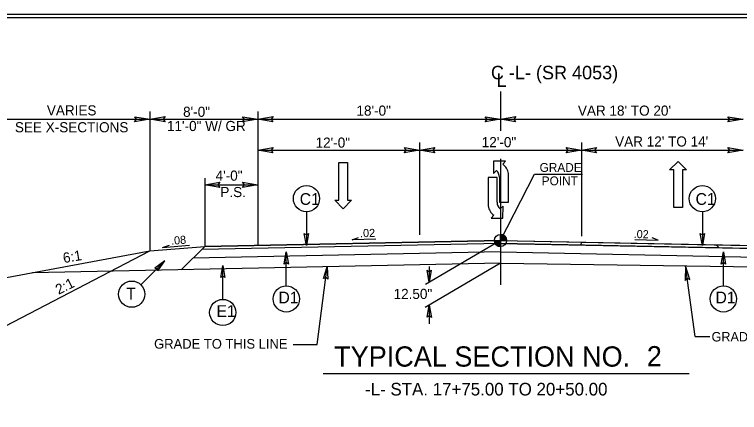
# Model space of a CAD drawing. Extents: x 981824 to 982276, y 44828 to 45204.
# Drawn here: x 982128.96 to 982171.98, y 45064.58 to 45088.17 of the extents above; entities that cross this region are included whole.
import ezdxf

# ---------------------------------------------------------------- set-up
doc = ezdxf.new("R2010")
doc.units = 0
for name, color, linetype in [('Default', 7, 'Continuous'), ('Old_Level_1', 7, 'Continuous'), ('Old_Level_11', 7, 'Continuous'), ('Old_Level_18', 7, 'Continuous'), ('Old_Level_2', 7, 'Continuous'), ('Old_Level_20', 7, 'Continuous'), ('Old_Level_21', 7, 'Continuous'), ('Old_Level_3', 7, 'Continuous'), ('Old_Level_50', 7, 'Continuous'), ('Prop Dimension Text', 7, 'Continuous'), ('Prop Lane Arrow CELL', 7, 'Continuous'), ('Prop Lane Arrow Through CELL', 7, 'Continuous'), ('Prop Roadway Profile Bench Mark Info Text', 7, 'Continuous'), ('Typical Terminator CELL', 7, 'Continuous')]:
    doc.layers.add(name, color=color, linetype=linetype)

msp = doc.modelspace()

# ---------------------------------------------------------------- linework, layer by layer
at = {"layer": 'Default'}
for points in [[(982150.402, 45074.86), (982149.001, 45074.811), (982149.368, 45074.949)], [(982165.76, 45074.838), (982167.161, 45074.789), (982166.795, 45074.928)]]:
    msp.add_lwpolyline(points, dxfattribs=at)
at = {"layer": 'Old_Level_1'}
for p, q in [((982157.794, 45083.599), (982157.794, 45081.277)), ((982136.994, 45082.429), (982136.994, 45074.163)), ((982143.394, 45082.429), (982143.394, 45074.486)), ((982127.455, 45081.961), (982136.994, 45081.961)), ((982136.994, 45081.961), (982143.394, 45081.961)), ((982143.394, 45081.961), (982157.794, 45081.961)), ((982157.794, 45081.961), (982172.194, 45081.961)), ((982152.994, 45080.576), (982152.994, 45075.114)), ((982162.594, 45080.576), (982162.594, 45075.027)), ((982143.394, 45080.13), (982152.994, 45080.13)), ((982152.994, 45080.13), (982162.594, 45080.13)), ((982162.594, 45080.13), (982172.194, 45080.13)), ((982157.794, 45079.618), (982157.794, 45072.147)), ((982157.794, 45074.774), (982159.823, 45078.716)), ((982140.245, 45078.468), (982140.245, 45074.423)), ((982140.245, 45078.078), (982143.394, 45078.078)), ((982157.794, 45074.774), (982157.794, 45075.134)), ((982157.794, 45074.774), (982140.255, 45074.424)), ((982157.794, 45074.774), (982153.354, 45072.168)), ((982157.434, 45074.774), (982157.794, 45074.774)), ((982157.793, 45074.414), (982157.794, 45074.774)), ((982157.794, 45074.774), (982157.793, 45074.414)), ((982157.794, 45074.774), (982175.392, 45074.422)), ((982158.154, 45074.774), (982157.794, 45074.774)), ((982136.994, 45074.163), (982140.255, 45074.424)), ((982137.743, 45074.362), (982139.34, 45074.504)), ((982137.743, 45074.362), (982138.165, 45074.504)), ((982140.245, 45074.423), (982138.856, 45073.042)), ((982157.794, 45074.602), (982140.069, 45074.248)), ((982157.791, 45074.601), (982175.567, 45074.247)), ((982127.455, 45069.205), (982136.994, 45074.163)), ((982127.455, 45072.384), (982136.994, 45074.163)), ((982157.794, 45074.105), (982139.536, 45073.718)), ((982157.794, 45074.105), (982176.095, 45073.719)), ((982157.794, 45073.422), (982130.033, 45072.865)), ((982157.794, 45073.422), (982153.319, 45070.796)), ((982157.794, 45073.422), (982184.096, 45073.052)), ((982146.923, 45068.604), (982147.517, 45073.216)), ((982153.567, 45073.232), (982153.567, 45072.292)), ((982169.345, 45069.089), (982168.78, 45073.267)), ((982153.567, 45070.941), (982153.567, 45069.828)), ((982169.345, 45069.089), (982170.214, 45069.089)), ((982145.505, 45068.604), (982146.923, 45068.604))]:
    msp.add_line(p, q, dxfattribs=at)
for points in [[(982157.797, 45075.134), (982157.797, 45075.134), (982157.797, 45074.774)], [(982157.804, 45075.134), (982157.804, 45074.774)], [(982157.811, 45075.133), (982157.811, 45074.774)], [(982157.819, 45075.133), (982157.819, 45074.774)], [(982157.826, 45075.132), (982157.826, 45074.774)], [(982157.833, 45075.132), (982157.833, 45074.774)], [(982157.84, 45075.131), (982157.84, 45074.774)], [(982157.847, 45075.13), (982157.847, 45074.774)], [(982157.855, 45075.129), (982157.855, 45074.774)], [(982157.862, 45075.128), (982157.862, 45074.774)], [(982157.869, 45075.126), (982157.869, 45074.774)], [(982157.876, 45075.124), (982157.876, 45074.774)], [(982157.883, 45075.123), (982157.883, 45074.774)], [(982157.435, 45074.774), (982157.435, 45074.735)], [(982157.443, 45074.774), (982157.443, 45074.692)], [(982157.45, 45074.774), (982157.45, 45074.667)], [(982157.457, 45074.774), (982157.457, 45074.645)], [(982157.464, 45074.774), (982157.464, 45074.628)], [(982157.471, 45074.774), (982157.471, 45074.613)], [(982157.479, 45074.774), (982157.479, 45074.6)], [(982157.486, 45074.774), (982157.486, 45074.587)], [(982157.493, 45074.774), (982157.493, 45074.576)], [(982157.5, 45074.774), (982157.5, 45074.565)], [(982157.507, 45074.774), (982157.507, 45074.556)], [(982157.515, 45074.774), (982157.515, 45074.547)], [(982157.522, 45074.774), (982157.522, 45074.538)], [(982157.529, 45074.774), (982157.529, 45074.53)], [(982157.536, 45074.774), (982157.536, 45074.522)], [(982157.543, 45074.774), (982157.543, 45074.515)], [(982157.551, 45074.774), (982157.551, 45074.508)], [(982157.558, 45074.774), (982157.558, 45074.502)], [(982157.565, 45074.774), (982157.565, 45074.496)], [(982157.572, 45074.774), (982157.572, 45074.49)], [(982157.579, 45074.774), (982157.579, 45074.484)], [(982157.587, 45074.774), (982157.587, 45074.48)], [(982157.594, 45074.774), (982157.594, 45074.475)], [(982157.601, 45074.774), (982157.601, 45074.47)], [(982157.608, 45074.774), (982157.608, 45074.465)], [(982157.615, 45074.774), (982157.615, 45074.461)], [(982157.623, 45074.774), (982157.623, 45074.457)], [(982157.63, 45074.774), (982157.63, 45074.453)], [(982157.637, 45074.774), (982157.637, 45074.45)], [(982157.644, 45074.774), (982157.644, 45074.447)], [(982157.651, 45074.774), (982157.651, 45074.444)], [(982157.659, 45074.774), (982157.659, 45074.44)], [(982157.666, 45074.774), (982157.666, 45074.437)], [(982157.673, 45074.774), (982157.673, 45074.435)], [(982157.68, 45074.774), (982157.68, 45074.432)], [(982157.687, 45074.774), (982157.687, 45074.43)], [(982157.695, 45074.774), (982157.695, 45074.428)], [(982157.702, 45074.774), (982157.702, 45074.426)], [(982157.709, 45074.774), (982157.709, 45074.424)], [(982157.716, 45074.774), (982157.716, 45074.423)], [(982157.723, 45074.774), (982157.723, 45074.421)], [(982157.731, 45074.774), (982157.731, 45074.42)], [(982157.738, 45074.774), (982157.738, 45074.419)], [(982157.745, 45074.774), (982157.745, 45074.417)], [(982157.752, 45074.774), (982157.752, 45074.416)], [(982157.759, 45074.774), (982157.759, 45074.416)], [(982157.767, 45074.774), (982157.767, 45074.415)], [(982157.774, 45074.774), (982157.774, 45074.415)], [(982157.781, 45074.774), (982157.781, 45074.414)], [(982157.788, 45074.774), (982157.788, 45074.414), (982157.788, 45074.414)], [(982157.891, 45075.12), (982157.891, 45074.774)], [(982157.898, 45075.119), (982157.898, 45074.774)], [(982157.905, 45075.116), (982157.905, 45074.774)], [(982157.912, 45075.114), (982157.912, 45074.774)], [(982157.919, 45075.112), (982157.919, 45074.774)], [(982157.927, 45075.108), (982157.927, 45074.774)], [(982157.934, 45075.105), (982157.934, 45074.774)], [(982157.941, 45075.102), (982157.941, 45074.774)], [(982157.948, 45075.099), (982157.948, 45074.774)], [(982157.955, 45075.096), (982157.955, 45074.774)], [(982157.963, 45075.092), (982157.963, 45074.774)], [(982157.97, 45075.088), (982157.97, 45074.774)], [(982157.977, 45075.084), (982157.977, 45074.774)], [(982157.984, 45075.08), (982157.984, 45074.774)], [(982157.991, 45075.075), (982157.991, 45074.774)], [(982157.999, 45075.07), (982157.999, 45074.774)], [(982158.006, 45075.064), (982158.006, 45074.774)], [(982158.013, 45075.06), (982158.013, 45074.774)], [(982158.02, 45075.054), (982158.02, 45074.774)], [(982158.027, 45075.048), (982158.027, 45074.774)], [(982158.035, 45075.041), (982158.035, 45074.774)], [(982158.042, 45075.035), (982158.042, 45074.774)], [(982158.049, 45075.028), (982158.049, 45074.774)], [(982158.056, 45075.02), (982158.056, 45074.774)], [(982158.063, 45075.012), (982158.063, 45074.774)], [(982158.071, 45075.004), (982158.071, 45074.774)], [(982158.078, 45074.995), (982158.078, 45074.774)], [(982158.085, 45074.985), (982158.085, 45074.774)], [(982158.092, 45074.975), (982158.092, 45074.774)], [(982158.099, 45074.964), (982158.099, 45074.774)], [(982158.107, 45074.952), (982158.107, 45074.774)], [(982158.114, 45074.939), (982158.114, 45074.774)], [(982158.121, 45074.924), (982158.121, 45074.774)], [(982158.128, 45074.907), (982158.128, 45074.774)], [(982158.135, 45074.887), (982158.135, 45074.774)], [(982158.143, 45074.862), (982158.143, 45074.774)], [(982158.15, 45074.825), (982158.15, 45074.774)]]:
    msp.add_lwpolyline(points, dxfattribs=at)
msp.add_circle((982157.793, 45074.774), 0.36, dxfattribs=at)
for start, end in [(359.9905, 89.9905), (179.9905, 269.9905)]:
    msp.add_arc((982157.793, 45074.774), 0.36, start, end, dxfattribs=at)
at = {"layer": 'Old_Level_11'}
for points in [[(982146.409, 45075.189), (982146.285, 45074.469), (982146.157, 45075.193), (982146.285, 45075.101)], [(982169.898, 45075.189), (982169.774, 45074.469), (982169.646, 45075.193), (982169.774, 45075.101)], [(982144.966, 45073.379), (982145.09, 45074.099), (982145.218, 45073.375), (982145.09, 45073.467)], [(982170.899, 45073.379), (982171.023, 45074.099), (982171.151, 45073.375), (982171.023, 45073.467)], [(982141.196, 45072.574), (982141.32, 45073.294), (982141.448, 45072.57), (982141.32, 45072.662)], [(982169.036, 45072.454), (982168.78, 45073.267), (982168.745, 45072.409), (982168.879, 45072.536)]]:
    msp.add_lwpolyline(points, close=True, dxfattribs=at)
at = {"layer": 'Old_Level_18'}
msp.add_lwpolyline([(982227.72, 45087.969), (982107.72, 45087.969), (982107.72, 45003.969), (982227.72, 45003.969)], close=True, dxfattribs=at)
at = {"layer": 'Old_Level_21'}
for points in [[(982157.794, 45074.602), (982140.069, 45074.248), (982140.245, 45074.423), (982157.794, 45074.774)], [(982157.794, 45074.774), (982170.592, 45074.518), (982170.767, 45074.343), (982157.791, 45074.601)], [(982162.594, 45074.678), (982175.392, 45074.422), (982175.567, 45074.247), (982162.591, 45074.505)]]:
    msp.add_lwpolyline(points, close=True, dxfattribs=at)
at = {"layer": 'Old_Level_3'}
msp.add_line((982159.823, 45078.716), (982162.669, 45078.716), dxfattribs=at)
at = {"layer": 'Old_Level_50'}
msp.add_lwpolyline([(982228.72, 45088.173), (982095.4, 45088.173), (982095.4, 45003.765), (982228.72, 45003.765)], close=True, dxfattribs=at)
at = {"layer": 'Prop Dimension Text'}
for p, q in [((982146.285, 45076.479), (982146.285, 45074.469)), ((982169.774, 45076.479), (982169.774, 45074.469)), ((982145.09, 45072.089), (982145.09, 45074.099)), ((982171.023, 45072.089), (982171.023, 45074.099)), ((982136.466, 45072.142), (982137.887, 45073.563)), ((982141.32, 45071.284), (982141.32, 45073.294))]:
    msp.add_line(p, q, dxfattribs=at)
for centre in [(982146.285, 45077.256), (982169.774, 45077.256), (982135.916, 45071.592), (982145.089, 45071.311), (982171.022, 45071.311), (982141.319, 45070.507)]:
    msp.add_circle(centre, 0.778, dxfattribs=at)
at = {"layer": 'Prop Lane Arrow CELL'}
for p, q in [((982158.099, 45079.469), (982157.387, 45079.469)), ((982157.387, 45079.469), (982157.387, 45078.749)), ((982157.931, 45079.293), (982158.099, 45079.469)), ((982157.387, 45078.749), (982157.555, 45078.917)), ((982158.267, 45077.053), (982158.267, 45078.741)), ((982157.067, 45078.509), (982157.067, 45076.821)), ((982157.595, 45078.509), (982157.067, 45078.509)), ((982157.595, 45077.045), (982157.595, 45078.509)), ((982157.739, 45078.517), (982157.739, 45077.053)), ((982157.739, 45077.053), (982158.267, 45077.053)), ((982157.947, 45076.813), (982157.779, 45076.645)), ((982157.939, 45076.093), (982157.947, 45076.813)), ((982157.403, 45076.269), (982157.235, 45076.101)), ((982157.235, 45076.101), (982157.939, 45076.093))]:
    msp.add_line(p, q, dxfattribs=at)
for centre, radius, start, end in [((982157.435, 45078.616), 0.84, 8.6761, 53.9878), ((982157.213, 45078.52), 0.524, 360, 49.6582), ((982158.117, 45077.043), 0.524, 180, 229.6582), ((982157.895, 45076.947), 0.84, 188.6761, 233.9878)]:
    msp.add_arc(centre, radius, start, end, dxfattribs=at)
at = {"layer": 'Prop Lane Arrow Through CELL'}
for p, q in [((982167.834, 45078.962), (982168.33, 45079.466)), ((982168.33, 45079.466), (982168.842, 45078.962)), ((982148.198, 45077.164), (982148.198, 45079.404)), ((982148.198, 45079.404), (982148.726, 45079.404)), ((982148.726, 45079.404), (982148.726, 45077.164)), ((982168.074, 45078.962), (982167.834, 45078.962)), ((982168.074, 45076.722), (982168.074, 45078.962)), ((982168.842, 45078.962), (982168.602, 45078.962)), ((982168.602, 45078.962), (982168.602, 45076.722)), ((982148.47, 45076.66), (982147.958, 45077.164)), ((982147.958, 45077.164), (982148.198, 45077.164)), ((982148.966, 45077.164), (982148.47, 45076.66)), ((982148.726, 45077.164), (982148.966, 45077.164)), ((982168.602, 45076.722), (982168.074, 45076.722))]:
    msp.add_line(p, q, dxfattribs=at)
at = {"layer": 'Prop Roadway Profile Bench Mark Info Text'}
msp.add_line((982147.279, 45066.892), (982168.999, 45066.892), dxfattribs=at)
at = {"layer": 'Typical Terminator CELL'}
for points in [[(982136.094, 45082.116), (982136.994, 45081.961), (982136.089, 45081.801), (982136.204, 45081.961)], [(982137.894, 45081.806), (982136.994, 45081.961), (982137.899, 45082.121), (982137.784, 45081.961)], [(982142.494, 45082.116), (982143.394, 45081.961), (982142.489, 45081.801), (982142.604, 45081.961)], [(982144.294, 45081.806), (982143.394, 45081.961), (982144.299, 45082.121), (982144.184, 45081.961)], [(982156.894, 45082.116), (982157.794, 45081.961), (982156.889, 45081.801), (982157.004, 45081.961)], [(982158.694, 45081.806), (982157.794, 45081.961), (982158.699, 45082.121), (982158.584, 45081.961)], [(982171.294, 45082.116), (982172.194, 45081.961), (982171.289, 45081.801), (982171.404, 45081.961)], [(982144.294, 45079.975), (982143.394, 45080.13), (982144.299, 45080.29), (982144.184, 45080.13)], [(982152.094, 45080.285), (982152.994, 45080.13), (982152.089, 45079.97), (982152.204, 45080.13)], [(982153.894, 45079.975), (982152.994, 45080.13), (982153.899, 45080.29), (982153.784, 45080.13)], [(982161.694, 45080.285), (982162.594, 45080.13), (982161.689, 45079.97), (982161.804, 45080.13)], [(982163.494, 45079.975), (982162.594, 45080.13), (982163.499, 45080.29), (982163.384, 45080.13)], [(982171.294, 45080.285), (982172.194, 45080.13), (982171.289, 45079.97), (982171.404, 45080.13)], [(982141.145, 45077.923), (982140.245, 45078.078), (982141.15, 45078.238), (982141.035, 45078.078)], [(982142.494, 45078.233), (982143.394, 45078.078), (982142.489, 45077.918), (982142.604, 45078.078)], [(982137.466, 45072.966), (982137.887, 45073.563), (982137.285, 45073.141), (982137.44, 45073.116)], [(982147.304, 45072.517), (982147.517, 45073.216), (982147.554, 45072.481), (982147.438, 45072.589)], [(982153.691, 45073.012), (982153.567, 45072.292), (982153.439, 45073.016), (982153.567, 45072.924)], [(982153.443, 45070.221), (982153.567, 45070.941), (982153.695, 45070.217), (982153.567, 45070.309)]]:
    msp.add_lwpolyline(points, close=True, dxfattribs=at)

# ---------------------------------------------------------------- texts
at = {"layer": 'Old_Level_1'}
for s, height, p in [('C -L- (SR 4053)', 0.8, (982157.229, 45084.331)), ('L', 0.8, (982157.561, 45083.88)), ('VARIES', 0.6, (982130.88, 45082.189)), ('8\'-0"', 0.6, (982138.964, 45082.106)), ('18\'-0"', 0.6, (982149.25, 45082.174)), ("VAR 18' TO 20'", 0.6, (982162.39, 45082.174)), ('SEE X-SECTIONS', 0.6, (982128.986, 45081.189)), ('11\'-0" W/ GR', 0.6, (982138.008, 45081.263)), ('12\'-0"', 0.6, (982146.827, 45080.278)), ('12\'-0"', 0.6, (982156.685, 45080.306)), ("VAR 12' TO 14'", 0.6, (982164.6, 45080.344)), ('4\'-0"', 0.6, (982140.893, 45078.319)), ('P.S.', 0.6, (982141.176, 45077.348)), ('12.50"', 0.6, (982151.454, 45071.305))]:
    msp.add_text(s, height=height, dxfattribs=at).set_placement(p)
for s, rotation, p in [('6:1', 9.4617, (982131.887, 45073.434)), ('2:1', 26.5646, (982131.578, 45071.551))]:
    msp.add_text(s, height=0.6, rotation=rotation, dxfattribs=at).set_placement(p)
at = {"layer": 'Old_Level_2'}
for s, rotation, p in [('.02  ', 1.144, (982149.468, 45074.969)), ('.02  ', 358.856, (982165.695, 45074.919)), ('.08', 4.5739, (982138.269, 45074.518))]:
    msp.add_text(s, height=0.48, rotation=rotation, dxfattribs=at).set_placement(p)
at = {"layer": 'Old_Level_20'}
for s, p in [('C1', (982145.884, 45076.886)), ('C1', (982169.372, 45076.886)), ('T ', (982135.587, 45071.274)), ('D1', (982144.623, 45071.047)), ('D1', (982170.556, 45071.047)), ('E1', (982140.947, 45070.242))]:
    msp.add_text(s, height=0.696, dxfattribs=at).set_placement(p)
at = {"layer": 'Old_Level_3'}
msp.add_text('GRADE TO THIS LINE', height=0.56063, rotation=360, dxfattribs=at).set_placement((982170.319, 45068.786))
for s, height, p in [('GRADE TO THIS LINE', 0.576, (982137.244, 45068.359)), ('TYPICAL SECTION NO.  ', 1.2, (982147.927, 45067.295)), ('2 ', 1.2, (982166.479, 45067.311))]:
    msp.add_text(s, height=height, dxfattribs=at).set_placement(p)
at = {"layer": 'Prop Dimension Text'}
for s, height, p in [('GRADE', 0.5248, (982160.117, 45078.842)), ('POINT', 0.5248, (982160.243, 45078.047)), (' -L- STA. 17+75.00 TO 20+50.00', 0.75, (982149.483, 45065.583))]:
    msp.add_text(s, height=height, dxfattribs=at).set_placement(p)

doc.saveas('drawing.dxf')
